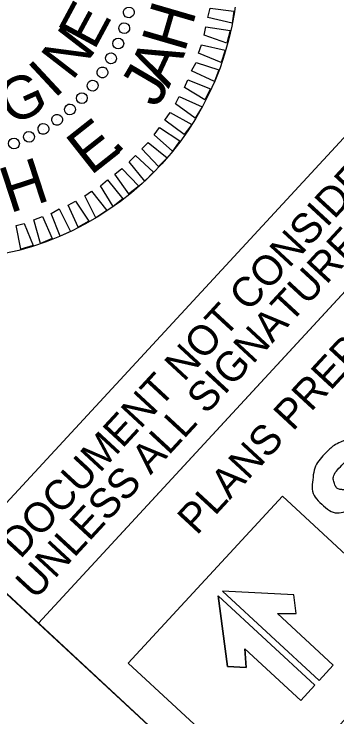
# Model space of a CAD drawing. Extents: x 1768274 to 1769121, y 999922 to 1000687.
# Drawn here: x 1768981.8 to 1768989.61, y 1000266.93 to 1000283.92 of the extents above; entities that cross this region are included whole.
import ezdxf

# ---------------------------------------------------------------- set-up
doc = ezdxf.new("R2010")
doc.units = 0
for name, color, linetype in [('Default', 7, 'Continuous'), ('E_NCDOT_Terrain_Model_Contour_Imported', 7, 'Continuous'), ('E_NCDOT_Terrain_Model_Contour_Major', 7, 'Continuous'), ('E_NCDOT_Terrain_Model_Points_Low', 7, 'Continuous'), ('E_NCDOT_Terrain_Model_Void', 7, 'Continuous')]:
    doc.layers.add(name, color=color, linetype=linetype)

msp = doc.modelspace()

# ---------------------------------------------------------------- linework, layer by layer
at = {"layer": 'Default'}
for points in [[(1768988.295, 1000272.266), (1768984.566, 1000268.232), (1768988.067, 1000264.996), (1768991.796, 1000269.03), (1768988.295, 1000272.266)], [(1768986.738, 1000269.863), (1768989.079, 1000267.699), (1768988.738, 1000267.331), (1768987.388, 1000268.579), (1768987.419, 1000268.127), (1768986.964, 1000268.149), (1768986.738, 1000269.863)]]:
    msp.add_lwpolyline(points, dxfattribs=at)
msp.add_lwpolyline([(1768986.843, 1000269.977), (1768989.184, 1000267.813), (1768989.525, 1000268.182), (1768988.175, 1000269.43), (1768988.628, 1000269.435), (1768988.57, 1000269.887)], close=True, dxfattribs=at)
at = {"layer": 'E_NCDOT_Terrain_Model_Contour_Imported'}
msp.add_lwpolyline([(1768737.288, 1000073.608), (1768947.711, 1000301.251), (1769102.655, 1000158.029), (1768892.232, 999930.385)], close=True, dxfattribs=at)
msp.add_circle((1768980.15, 1000285.055), 7.065, dxfattribs=at)
at = {"layer": 'E_NCDOT_Terrain_Model_Contour_Major'}
for p, q in [((1769102.655, 1000158.029), (1768947.714, 1000301.255)), ((1768995.967, 1000283.887), (1768982.392, 1000269.2)), ((1768995.968, 1000283.887), (1768982.392, 1000269.2)), ((1768982.392, 1000269.2), (1768982.392, 1000269.2))]:
    msp.add_line(p, q, dxfattribs=at)
for points in [[(1768980.521, 1000270.929), (1768994.098, 1000285.617), (1768995.969, 1000283.888), (1768982.392, 1000269.2)], [(1768984.566, 1000268.232), (1768988.295, 1000272.266), (1768991.796, 1000269.03), (1768988.067, 1000264.996)]]:
    msp.add_lwpolyline(points, close=True, dxfattribs=at)
msp.add_lwpolyline([(1768986.964, 1000268.149), (1768987.419, 1000268.127), (1768987.388, 1000268.579), (1768988.738, 1000267.331), (1768989.079, 1000267.699), (1768986.738, 1000269.863), (1768986.964, 1000268.149)], dxfattribs=at)
for points in [[(1768989.702, 1000273.579), (1768989.832, 1000273.634), (1768989.977, 1000273.663), (1768990.138, 1000273.666), (1768990.138, 1000273.666), (1768990.167, 1000273.184), (1768990.167, 1000273.184), (1768989.989, 1000273.197), (1768989.832, 1000273.13), (1768989.696, 1000272.982), (1768989.56, 1000272.835), (1768989.509, 1000272.707), (1768989.544, 1000272.599), (1768989.579, 1000272.492), (1768989.64, 1000272.435), (1768989.729, 1000272.428), (1768989.818, 1000272.422), (1768989.944, 1000272.48), (1768990.105, 1000272.604), (1768990.266, 1000272.744), (1768990.45, 1000272.835), (1768990.656, 1000272.879), (1768990.863, 1000272.923), (1768991.064, 1000272.855), (1768991.261, 1000272.673), (1768991.414, 1000272.531), (1768991.484, 1000272.342), (1768991.47, 1000272.104), (1768991.455, 1000271.866), (1768991.365, 1000271.657), (1768991.199, 1000271.477), (1768991.041, 1000271.306), (1768990.883, 1000271.187), (1768990.726, 1000271.12), (1768990.569, 1000271.053), (1768990.41, 1000271.018), (1768990.249, 1000271.015), (1768990.249, 1000271.015), (1768990.22, 1000271.497), (1768990.22, 1000271.497), (1768990.398, 1000271.484), (1768990.587, 1000271.568), (1768990.785, 1000271.748), (1768990.936, 1000271.912), (1768990.994, 1000272.047), (1768990.959, 1000272.155), (1768990.924, 1000272.262), (1768990.852, 1000272.329), (1768990.742, 1000272.356), (1768990.632, 1000272.382), (1768990.493, 1000272.322), (1768990.324, 1000272.174), (1768990.171, 1000272.042), (1768990, 1000271.951), (1768989.809, 1000271.899), (1768989.619, 1000271.847), (1768989.43, 1000271.908), (1768989.243, 1000272.081), (1768989.073, 1000272.238), (1768989.001, 1000272.434), (1768989.028, 1000272.668), (1768989.054, 1000272.903), (1768989.135, 1000273.094), (1768989.271, 1000273.241), (1768989.429, 1000273.412), (1768989.573, 1000273.525), (1768989.702, 1000273.579)], [(1768989.702, 1000273.579), (1768989.573, 1000273.525), (1768989.429, 1000273.412), (1768989.271, 1000273.241), (1768989.135, 1000273.094), (1768989.054, 1000272.903), (1768989.028, 1000272.668), (1768989.001, 1000272.434), (1768989.073, 1000272.238), (1768989.243, 1000272.081), (1768989.43, 1000271.908), (1768989.619, 1000271.847), (1768989.809, 1000271.899), (1768990, 1000271.951), (1768990.171, 1000272.042), (1768990.324, 1000272.174), (1768990.493, 1000272.322), (1768990.632, 1000272.382), (1768990.742, 1000272.356), (1768990.852, 1000272.329), (1768990.924, 1000272.262), (1768990.959, 1000272.155), (1768990.994, 1000272.047), (1768990.936, 1000271.912), (1768990.785, 1000271.748), (1768990.587, 1000271.568), (1768990.398, 1000271.484), (1768990.22, 1000271.497)], [(1768990.249, 1000271.015), (1768990.41, 1000271.018), (1768990.569, 1000271.053), (1768990.726, 1000271.12), (1768990.883, 1000271.187), (1768991.041, 1000271.306), (1768991.199, 1000271.477), (1768991.365, 1000271.657), (1768991.455, 1000271.866), (1768991.47, 1000272.104), (1768991.484, 1000272.342), (1768991.414, 1000272.531), (1768991.261, 1000272.673), (1768991.064, 1000272.855), (1768990.863, 1000272.923), (1768990.656, 1000272.879), (1768990.45, 1000272.835), (1768990.266, 1000272.744), (1768990.105, 1000272.604), (1768989.944, 1000272.48), (1768989.818, 1000272.422), (1768989.729, 1000272.428), (1768989.64, 1000272.435), (1768989.579, 1000272.492), (1768989.544, 1000272.599), (1768989.509, 1000272.707), (1768989.56, 1000272.835), (1768989.696, 1000272.982), (1768989.832, 1000273.13), (1768989.989, 1000273.197), (1768990.167, 1000273.184)]]:
    msp.add_open_spline(points, degree=3, dxfattribs=at)
at = {"layer": 'E_NCDOT_Terrain_Model_Points_Low'}
msp.add_lwpolyline([(1768986.843, 1000269.977), (1768989.184, 1000267.813), (1768989.525, 1000268.182), (1768988.175, 1000269.43), (1768988.628, 1000269.435), (1768988.57, 1000269.887), (1768986.843, 1000269.977)], dxfattribs=at)
at = {"layer": 'E_NCDOT_Terrain_Model_Void'}
for p, q in [((1768984.474, 1000283.578), (1768984.474, 1000283.578)), ((1768984.334, 1000283.212), (1768984.334, 1000283.212)), ((1768984.154, 1000282.857), (1768984.154, 1000282.857)), ((1768983.936, 1000282.513), (1768983.936, 1000282.513)), ((1768983.71, 1000282.189), (1768983.71, 1000282.189)), ((1768983.445, 1000281.889), (1768983.445, 1000281.889)), ((1768983.153, 1000281.613), (1768983.153, 1000281.613)), ((1768982.841, 1000281.369), (1768982.841, 1000281.369)), ((1768982.521, 1000281.144), (1768982.521, 1000281.144)), ((1768982.168, 1000280.95), (1768982.168, 1000280.95))]:
    msp.add_line(p, q, dxfattribs=at)
for points in [[(1768986.548, 1000284.065), (1768987.117, 1000283.997), (1768987.083, 1000283.706), (1768986.492, 1000283.844)], [(1768986.443, 1000283.617), (1768987.032, 1000283.53), (1768986.948, 1000283.224), (1768986.406, 1000283.415)], [(1768986.338, 1000283.181), (1768986.91, 1000283.049), (1768986.812, 1000282.755), (1768986.262, 1000282.978)], [(1768986.206, 1000282.757), (1768986.754, 1000282.573), (1768986.649, 1000282.298), (1768986.092, 1000282.553)], [(1768986.01, 1000282.331), (1768986.554, 1000282.114), (1768986.422, 1000281.851), (1768985.928, 1000282.147)], [(1768985.801, 1000281.93), (1768986.352, 1000281.681), (1768986.188, 1000281.41), (1768985.705, 1000281.758)], [(1768985.578, 1000281.541), (1768986.104, 1000281.253), (1768985.921, 1000281.013), (1768985.45, 1000281.362)], [(1768985.321, 1000281.183), (1768985.817, 1000280.861), (1768985.634, 1000280.609), (1768985.193, 1000281.004)], [(1768985.046, 1000280.818), (1768985.511, 1000280.45), (1768985.301, 1000280.236), (1768984.891, 1000280.664)], [(1768984.743, 1000280.503), (1768985.177, 1000280.102), (1768984.967, 1000279.888), (1768984.588, 1000280.349)], [(1768984.414, 1000280.188), (1768984.823, 1000279.76), (1768984.58, 1000279.576), (1768984.239, 1000280.052)], [(1768984.064, 1000279.916), (1768984.436, 1000279.461), (1768984.199, 1000279.271), (1768983.895, 1000279.775)], [(1768983.675, 1000279.644), (1768984.048, 1000279.175), (1768983.784, 1000278.997), (1768983.512, 1000279.534)], [(1768983.292, 1000279.403), (1768983.614, 1000278.92), (1768983.355, 1000278.774), (1768983.115, 1000279.306)], [(1768982.894, 1000279.214), (1768983.172, 1000278.671), (1768982.919, 1000278.558), (1768982.705, 1000279.103)], [(1768982.489, 1000279.03), (1768982.728, 1000278.499), (1768982.443, 1000278.378), (1768982.279, 1000278.951)], [(1768982.051, 1000278.865), (1768982.265, 1000278.332), (1768981.966, 1000278.237), (1768981.853, 1000278.812)]]:
    msp.add_lwpolyline(points, close=True, dxfattribs=at)
for centre, major_axis in [((1768984.58, 1000283.965), (0.127, -0.031)), ((1768984.469, 1000283.583), (0.124, -0.042)), ((1768984.324, 1000283.211), (0.12, -0.053)), ((1768984.148, 1000282.854), (0.115, -0.063)), ((1768983.942, 1000282.514), (0.109, -0.073)), ((1768983.706, 1000282.193), (0.102, -0.082)), ((1768983.444, 1000281.893), (0.0947, -0.0906)), ((1768983.156, 1000281.618), (0.0864, -0.0985)), ((1768982.845, 1000281.369), (0.077, -0.106)), ((1768982.514, 1000281.147), (0.068, -0.112)), ((1768982.165, 1000280.956), (0.058, -0.118)), ((1768981.801, 1000280.795), (0.048, -0.122))]:
    msp.add_ellipse(centre, major_axis=major_axis, ratio=0.999708, dxfattribs=at)

# ---------------------------------------------------------------- texts
at = {"layer": 'E_NCDOT_Terrain_Model_Contour_Major'}
for s, height, p in [('DOCUMENT NOT CONSIDERED FINAL', 0.72007, (1768981.954, 1000270.734)), ('UNLESS ALL SIGNATURES COMPLETED', 0.72007, (1768982.309, 1000269.744)), ('PLANS PREPARED BY:', 0.72001, (1768986.222, 1000271.305)), ('NC FIRM LICENSE No: C-5176', 0.92363, (1768989.556, 1000263.89))]:
    msp.add_text(s, height=height, rotation=47.2512, dxfattribs=at).set_placement(p)
at = {"layer": 'E_NCDOT_Terrain_Model_Void'}
for s, height, rotation, p in [('046981', 1.0918, 47.2512, (1768979.614, 1000282.327)), ('E', 1.029, 61.663, (1768983.742, 1000283.027)), ('H', 1.1, 73.7505, (1768985.93, 1000282.973)), ('N', 1.027, 52.3076, (1768983.21, 1000282.292)), ('A', 1.096, 64.9102, (1768985.542, 1000282.109)), ('I', 1.026, 42.9524, (1768982.777, 1000281.862)), ('J', 1.094, 59.6524, (1768985.25, 1000281.627)), ('G', 1.033, 24.2415, (1768981.713, 1000281.222)), ('E', 1.093, 38.3089, (1768983.654, 1000280.004)), ('.', 1.092, 45.4183, (1768984.251, 1000280.477)), ('H', 1.101, 18.1246, (1768981.697, 1000279.103))]:
    msp.add_text(s, height=height, rotation=rotation, dxfattribs=at).set_placement(p)

doc.saveas('drawing.dxf')
